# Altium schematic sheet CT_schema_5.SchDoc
size 386 x 355 mm
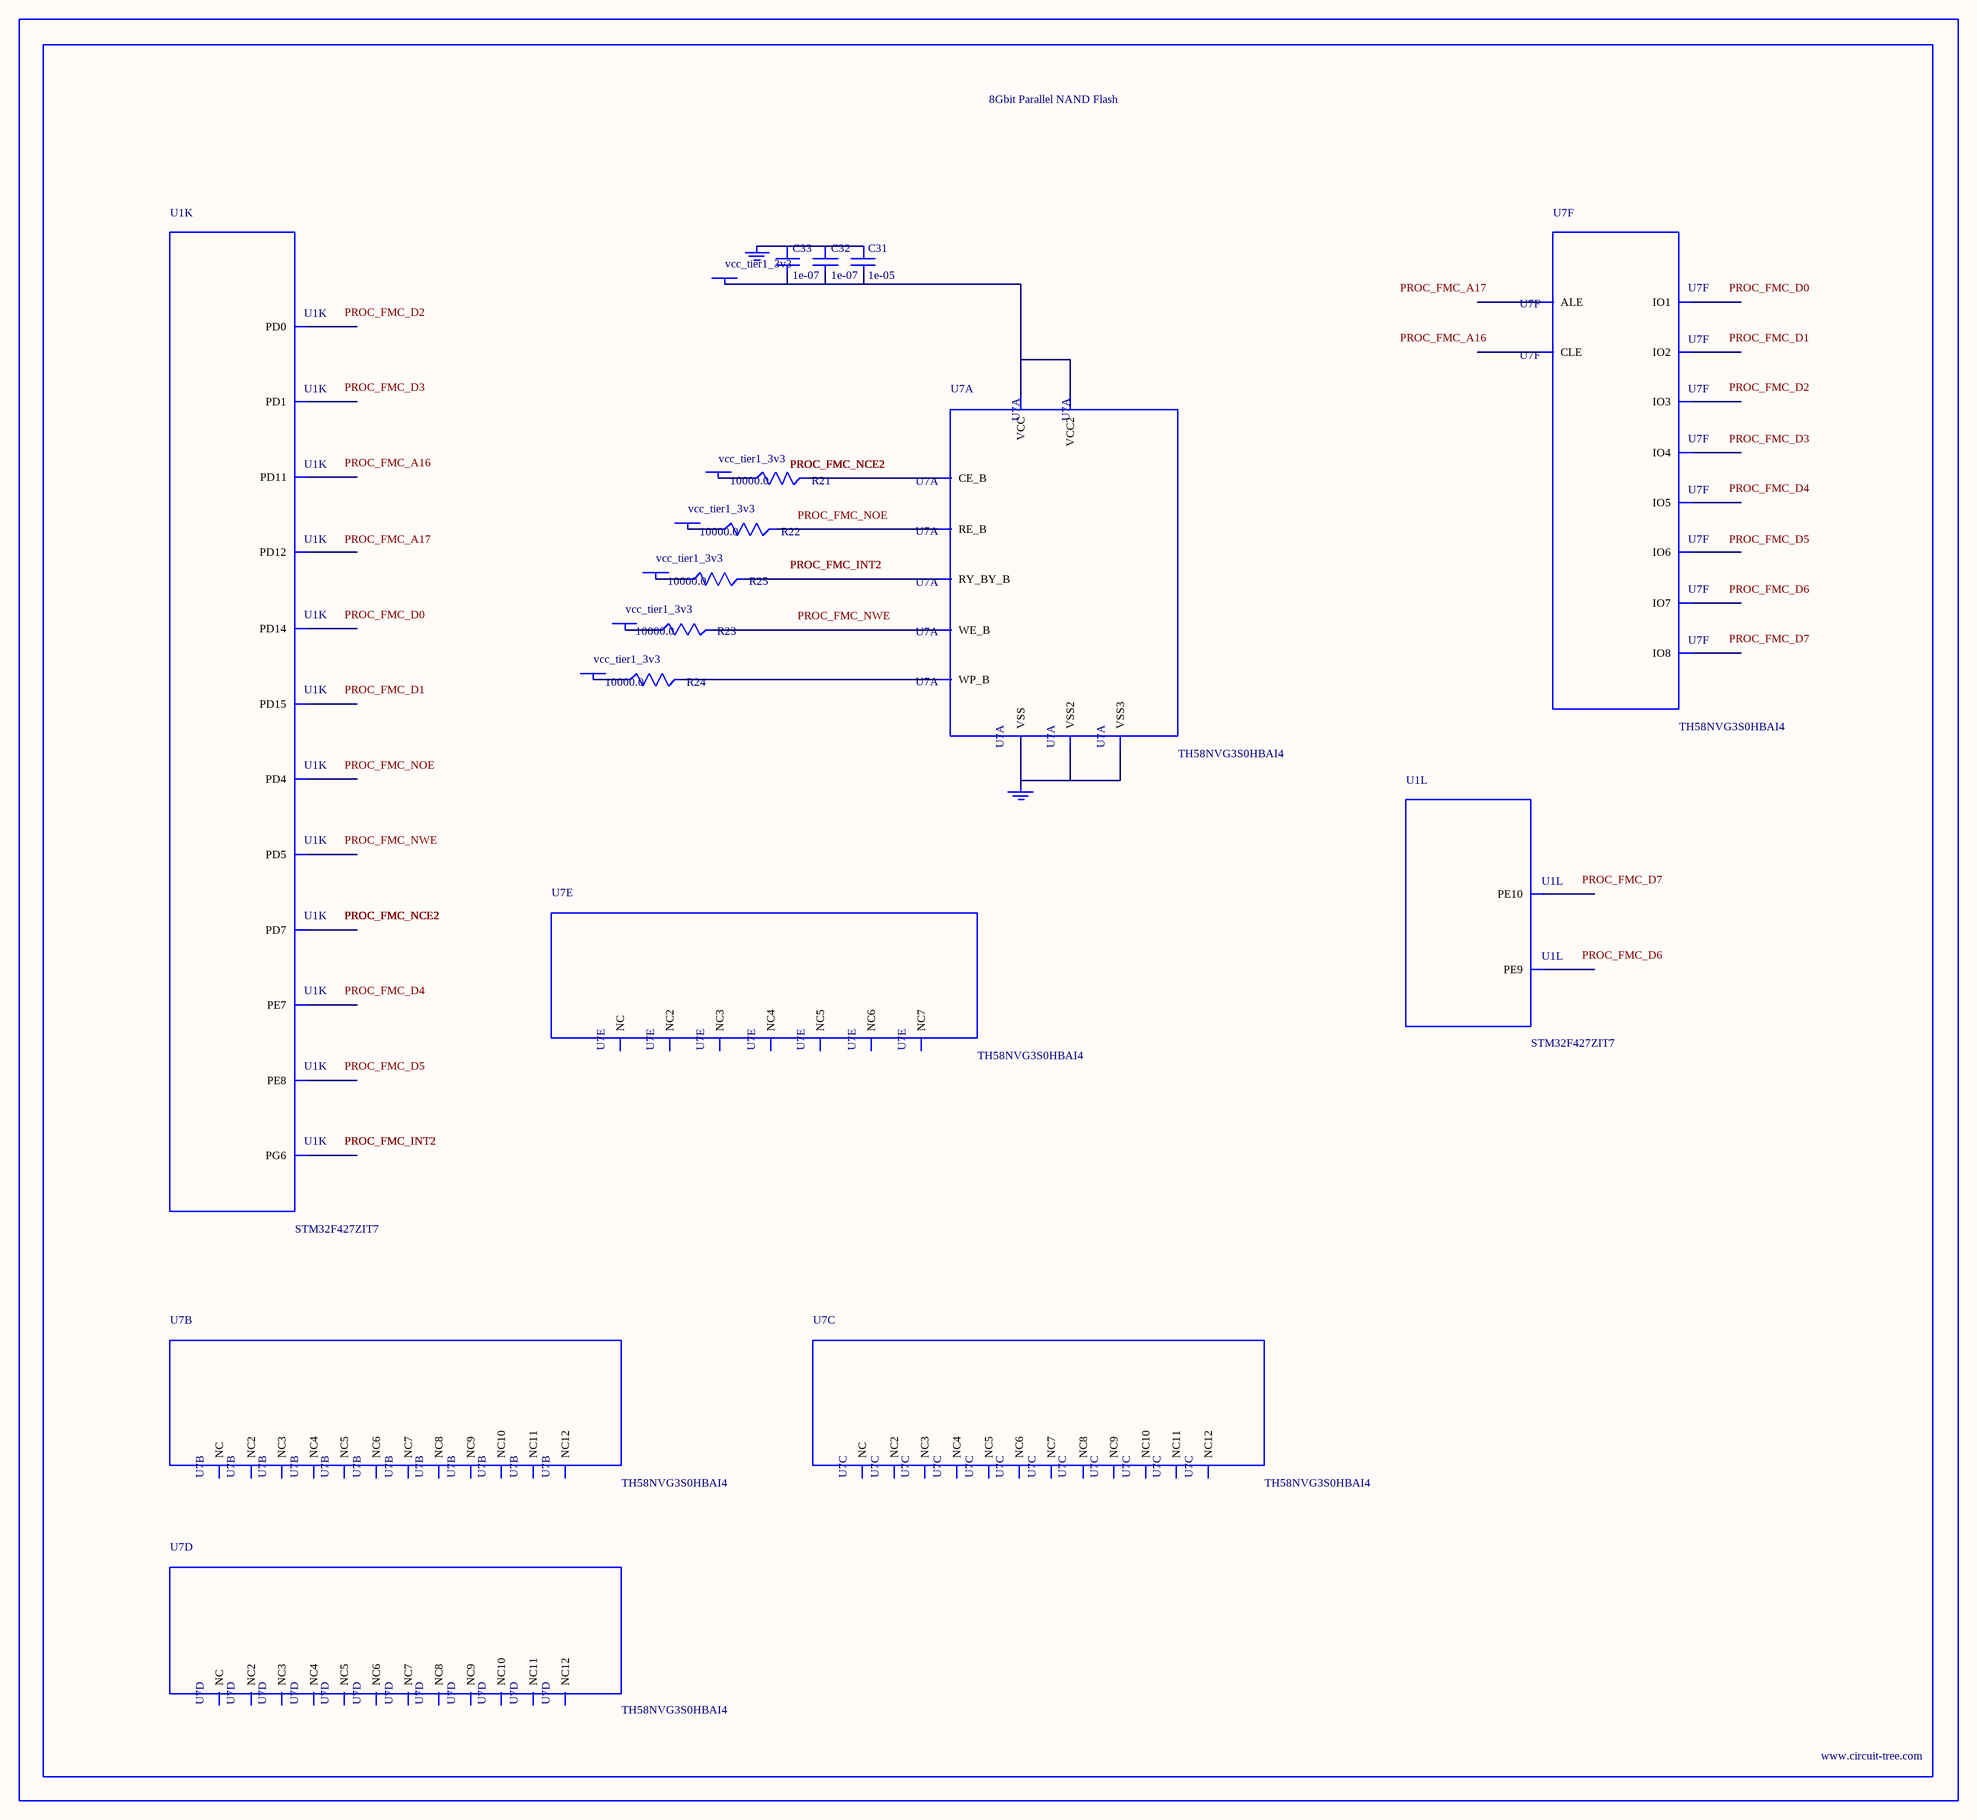
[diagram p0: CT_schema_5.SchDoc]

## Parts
BORDER4  (no value)
C31  1e-05  [C0805]
C32  1e-07  [C0402]
C33  1e-07  [C0402]
GND_INSTANCE_4_0  (no value)
GND_INSTANCE_4_1  (no value)
POWER_INSTANCE_4_0  vcc_tier1_3v3
POWER_INSTANCE_4_1  vcc_tier1_3v3
POWER_INSTANCE_4_2  vcc_tier1_3v3
POWER_INSTANCE_4_3  vcc_tier1_3v3
POWER_INSTANCE_4_4  vcc_tier1_3v3
POWER_INSTANCE_4_5  vcc_tier1_3v3
R21  10000.0  [R0603]
R22  10000.0  [R0603]
R23  10000.0  [R0603]
R24  10000.0  [R0603]
R25  10000.0  [R0603]
U1  STM32F427ZIT7  [LQFP144]  (parts K,L of 13)
U7  TH58NVG3S0HBAI4  [TH58NVG3S0HBAI4]  (parts A,B,C,D,E,F of 6)

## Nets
NetC31_1: C31.1 C32.1 C33.1 GND_INSTANCE_4_0.0(GND)
NetC31_2: C31.2 C32.2 C33.2 POWER_INSTANCE_4_5.0(PWR) U7.H8(VCC) U7.J6(VCC2)
NetGND_INSTANCE_4_1_0: GND_INSTANCE_4_1.0(GND) U7.C5(VSS) U7.K3(VSS2) U7.K8(VSS3)
NetPOWER_INSTANCE_4_0_0: POWER_INSTANCE_4_0.0(PWR) R21.1
NetPOWER_INSTANCE_4_1_0: POWER_INSTANCE_4_1.0(PWR) R22.1
NetPOWER_INSTANCE_4_2_0: POWER_INSTANCE_4_2.0(PWR) R23.1
NetPOWER_INSTANCE_4_3_0: POWER_INSTANCE_4_3.0(PWR) R24.1
NetPOWER_INSTANCE_4_4_0: POWER_INSTANCE_4_4.0(PWR) R25.1
NetR21_2: R21.2 U7.C6(CE_B)
NetR22_2: R22.2 U7.D4(RE_B)
NetR23_2: R23.2 U7.C7(WE_B)
NetR24_2: R24.2 U7.C3(WP_B)
NetR25_2: R25.2 U7.C8(RY_BY_B)

Not connected (* = marked no-connect by the designer): U1 58(PE7) 59(PE8) 60(PE9) 63(PE10) 80(PD11) 81(PD12) 85(PD14) 86(PD15) 91(PG6) 114(PD0) 115(PD1) 118(PD4) 119(PD5) 123(PD7); U7 A1(NC) A2(NC3) A9(NC4) A10(NC2) B1(NC5) B9(NC7) B10(NC6) C4(ALE) D3(NC8) D5(CLE) D6(NC9) D7(NC10) D8(NC11) E3(NC12) E4(NC) E5(NC2) E6(NC3) E7(NC4) E8(NC5) F3(NC6) F4(NC7) F5(NC8) F6(NC9) F7(NC10) F8(NC11) G3(NC12) G4(NC) G5(NC2) G6(NC3) G7(NC4) G8(NC5) H3(NC6) H4(IO1) H5(NC7) H6(NC8) H7(NC9) J3(NC10) J4(IO2) J5(NC11) J7(IO6) J8(IO8) K4(IO3) K5(IO4) K6(IO5) K7(IO7) L1(NC12) L2(NC2) L9(NC3) L10(NC) M1(NC4) M2(NC6) M9(NC7) M10(NC5)

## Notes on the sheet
- Labels drawn without touching a wire or pin: PROC_FMC_A16, PROC_FMC_A17, PROC_FMC_D0, PROC_FMC_D1, PROC_FMC_D2, PROC_FMC_D3, PROC_FMC_D4, PROC_FMC_D5, PROC_FMC_D6, PROC_FMC_D7, PROC_FMC_NOE, PROC_FMC_NWE

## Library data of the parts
BORDER4 = BORDER_PAGE4
C31 = C0805C106K8RACTU
C32 C33 = C0402C104K3RACTU
GND_INSTANCE_4_0 GND_INSTANCE_4_1 = GND
POWER_INSTANCE_4_0-POWER_INSTANCE_4_5 = PWR
R21-R25 = RC0603JR-0710KL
